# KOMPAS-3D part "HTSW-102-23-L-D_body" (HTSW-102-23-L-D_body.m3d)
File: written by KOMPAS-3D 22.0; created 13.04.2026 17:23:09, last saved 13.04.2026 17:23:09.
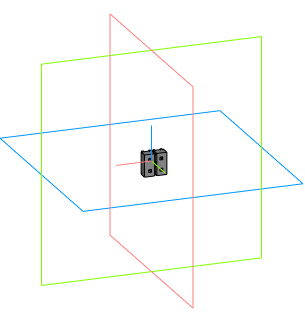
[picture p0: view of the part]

Document properties: Автор: Andrey; Полное имя файла: C:\Users\User1\Documents\HTSW-102-23-L-D_body.m3d

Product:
- Part/product: HTSW-102-23-L-D_body
    Комментарий: HTSW-102-23-L-D_body

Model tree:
1. Операция без истории:1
